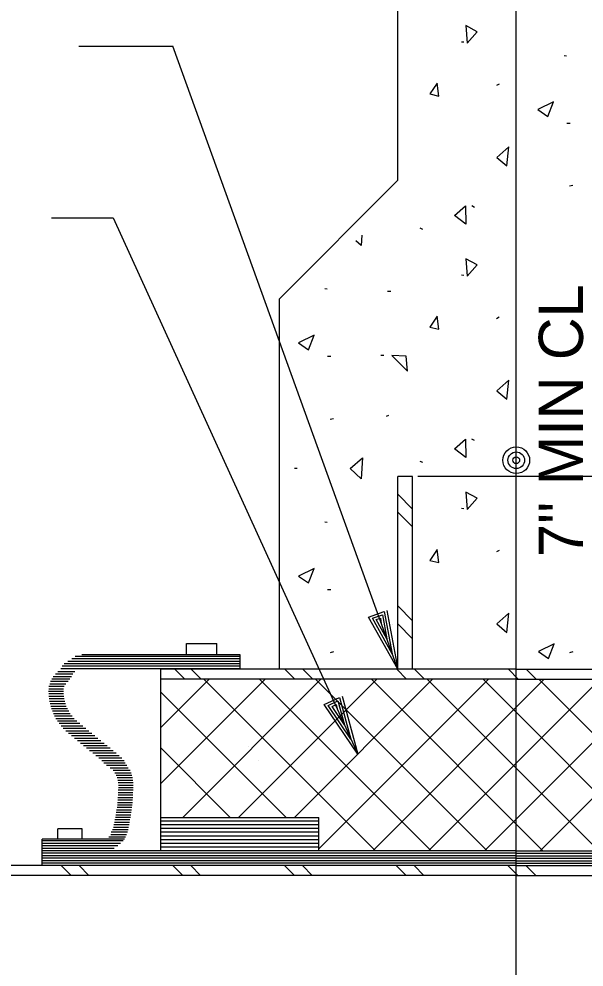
# Model space of a CAD drawing. Extents: x 22339.2 to 22413.4, y 22369.6 to 22418.8.
# Drawn here: x 22343.853 to 22346.238, y 22396.66 to 22400.659 of the extents above; entities that cross this region are included whole.
import ezdxf

# ---------------------------------------------------------------- set-up
doc = ezdxf.new("R2010")
doc.units = 0
for name, color, linetype in [('Level 1', 7, 'Continuous'), ('Level 2', 7, 'Continuous'), ('Level 4', 7, 'Continuous'), ('Level 44', 7, 'Continuous'), ('Level 7', 7, 'Continuous'), ('Level 8', 7, 'Continuous')]:
    doc.layers.add(name, color=color, linetype=linetype)

msp = doc.modelspace()

# ---------------------------------------------------------------- linework, layer by layer
at = {"layer": 'Level 1'}
for p, q in [((22345.9524, 22393.1147), (22345.9524, 22402.6063)), ((22345.4288, 22398.1058), (22345.4288, 22398.1058)), ((22344.5612, 22397.9773), (22344.5612, 22398.0249)), ((22344.5612, 22398.0249), (22344.6886, 22398.0249)), ((22344.6886, 22397.9773), (22344.6886, 22398.0249)), ((22345.4524, 22398.0406), (22345.4524, 22398.0406)), ((22344.4524, 22397.15), (22344.4524, 22397.9156)), ((22345.9524, 22397.9156), (22344.4524, 22397.9156)), ((22345.9524, 22397.9156), (22347.4524, 22397.9156)), ((22345.9524, 22397.874), (22344.4524, 22397.874)), ((22345.9524, 22397.874), (22347.4524, 22397.874)), ((22344.8216, 22397.5887), (22344.8216, 22397.5887)), ((22344.8627, 22397.5329), (22344.8627, 22397.5329)), ((22345.1191, 22397.275), (22344.4524, 22397.275)), ((22345.1191, 22397.2594), (22344.4524, 22397.2594)), ((22345.1191, 22397.2438), (22344.4524, 22397.2438)), ((22344.0172, 22397.1997), (22344.0172, 22397.2426)), ((22344.1208, 22397.2426), (22344.0172, 22397.2426)), ((22344.1208, 22397.1997), (22344.1208, 22397.2426)), ((22345.1191, 22397.2281), (22344.4524, 22397.2281)), ((22345.1191, 22397.2125), (22344.4524, 22397.2125)), ((22345.1191, 22397.1969), (22344.4524, 22397.1969)), ((22345.1191, 22397.1813), (22344.4524, 22397.1813)), ((22345.1191, 22397.1656), (22344.4524, 22397.1656))]:
    msp.add_line(p, q, dxfattribs=at)
at = {"layer": 'Level 2'}
for p, q in [((22344.1059, 22400.5431), (22344.5026, 22400.5431)), ((22345.4524, 22397.9156), (22344.5026, 22400.5431)), ((22345.4524, 22397.9156), (22345.4524, 22398.7281)), ((22345.5149, 22398.7281), (22345.4524, 22398.7281)), ((22345.5149, 22397.9156), (22345.5149, 22398.7281)), ((22346.4524, 22398.7281), (22345.5373, 22398.7281)), ((22344.7869, 22397.9773), (22344.1184, 22397.9773)), ((22344.7869, 22397.9156), (22344.7869, 22397.9773)), ((22344.4524, 22397.15), (22344.4524, 22397.2906)), ((22344.4524, 22397.2906), (22345.1191, 22397.2906)), ((22345.1191, 22397.15), (22345.1191, 22397.2906)), ((22343.9511, 22397.0875), (22343.9511, 22397.1997)), ((22344.2992, 22397.1997), (22343.9511, 22397.1997)), ((22345.9524, 22397.15), (22343.9511, 22397.15)), ((22345.9524, 22397.1396), (22343.9511, 22397.1396)), ((22345.9524, 22397.1292), (22343.9511, 22397.1292)), ((22345.9524, 22397.15), (22347.9537, 22397.15)), ((22345.9524, 22397.1396), (22347.9537, 22397.1396)), ((22345.9524, 22397.1292), (22347.9537, 22397.1292)), ((22345.9524, 22397.0875), (22339.2857, 22397.0875)), ((22345.9524, 22397.1188), (22343.9511, 22397.1188)), ((22345.9524, 22397.1083), (22343.9511, 22397.1083)), ((22345.9524, 22397.0979), (22343.9511, 22397.0979)), ((22345.9524, 22397.1188), (22347.9537, 22397.1188)), ((22345.9524, 22397.1083), (22347.9537, 22397.1083)), ((22345.9524, 22397.0979), (22347.9537, 22397.0979)), ((22345.9524, 22397.0875), (22352.5966, 22397.0875)), ((22345.9524, 22397.0458), (22339.315, 22397.0458)), ((22345.9524, 22397.0458), (22352.587, 22397.0458))]:
    msp.add_line(p, q, dxfattribs=at)
for points in [[(22343.9912, 22399.8197), (22344.2517, 22399.8197), (22345.2832, 22397.5579)], [(22345.4065, 22398.1642), (22345.4524, 22397.9156), (22345.3288, 22398.1361), (22345.3952, 22398.1601), (22345.4288, 22397.9808), (22345.3449, 22398.1306), (22345.3876, 22398.146), (22345.4062, 22398.0435), (22345.3611, 22398.1251), (22345.3787, 22398.1314), (22345.3826, 22398.1087)], [(22344.7857, 22397.9699), (22344.0912, 22397.9699)], [(22344.7857, 22397.9282), (22344.0363, 22397.9282)], [(22344.7857, 22397.9387), (22344.0449, 22397.9387)], [(22344.7857, 22397.9491), (22344.0601, 22397.9491)], [(22344.7857, 22397.9595), (22344.0759, 22397.9595)], [(22344.075, 22397.8844), (22343.9982, 22397.8844)], [(22344.0808, 22397.8948), (22344.0073, 22397.8948)], [(22344.0898, 22397.9052), (22344.0176, 22397.9052)], [(22344.7857, 22397.9178), (22344.0299, 22397.9178)], [(22344.0518, 22397.8531), (22343.9834, 22397.8531)], [(22344.0615, 22397.8636), (22343.986, 22397.8636)], [(22344.0686, 22397.874), (22343.9918, 22397.874)], [(22344.0411, 22397.8219), (22343.9786, 22397.8219)], [(22344.0415, 22397.8323), (22343.9789, 22397.8323)], [(22344.0415, 22397.8115), (22343.9789, 22397.8115)], [(22344.0415, 22397.8115), (22343.9789, 22397.8115)], [(22344.0446, 22397.8427), (22343.9796, 22397.8427)], [(22344.0425, 22397.8011), (22343.9796, 22397.8011)], [(22344.0425, 22397.8011), (22343.9796, 22397.8011)], [(22344.0441, 22397.7906), (22343.9808, 22397.7906)], [(22344.0441, 22397.7906), (22343.9808, 22397.7906)], [(22344.0465, 22397.7802), (22343.9825, 22397.7802)], [(22344.0465, 22397.7802), (22343.9825, 22397.7802)], [(22344.0495, 22397.7698), (22343.9847, 22397.7698)], [(22344.0495, 22397.7698), (22343.9847, 22397.7698)], [(22345.2173, 22397.8019), (22345.2832, 22397.5579), (22345.1421, 22397.7676), (22345.2064, 22397.7969), (22345.2544, 22397.621), (22345.1587, 22397.7634), (22345.1999, 22397.7823), (22345.2268, 22397.6817), (22345.1752, 22397.7593), (22345.1922, 22397.767), (22345.198, 22397.7447)], [(22344.0533, 22397.7594), (22343.9874, 22397.7594)], [(22344.058, 22397.749), (22343.9906, 22397.749)], [(22344.0635, 22397.7386), (22343.9944, 22397.7386)], [(22344.0701, 22397.7281), (22343.9987, 22397.7281)], [(22344.0778, 22397.7177), (22344.0037, 22397.7177)], [(22344.0869, 22397.7073), (22344.0094, 22397.7073)], [(22344.0977, 22397.6969), (22344.0158, 22397.6969)], [(22344.1102, 22397.6865), (22344.023, 22397.6865)], [(22344.123, 22397.6761), (22344.0311, 22397.6761)], [(22344.1358, 22397.6656), (22344.0402, 22397.6656)], [(22344.1485, 22397.6552), (22344.0506, 22397.6552)], [(22344.1613, 22397.6448), (22344.0625, 22397.6448)], [(22344.1741, 22397.6344), (22344.0752, 22397.6344)], [(22344.1868, 22397.624), (22344.088, 22397.624)], [(22344.1996, 22397.6136), (22344.1008, 22397.6136)], [(22344.2124, 22397.6031), (22344.1135, 22397.6031)], [(22344.2251, 22397.5927), (22344.1263, 22397.5927)], [(22344.2379, 22397.5823), (22344.139, 22397.5823)], [(22344.2507, 22397.5719), (22344.1518, 22397.5719)], [(22344.2634, 22397.5615), (22344.1646, 22397.5615)], [(22344.2762, 22397.5511), (22344.1774, 22397.5511)], [(22344.2875, 22397.5406), (22344.1901, 22397.5406)], [(22344.297, 22397.5302), (22344.2029, 22397.5302)], [(22344.3012, 22397.5198), (22344.2117, 22397.5198)], [(22344.3083, 22397.5094), (22344.2231, 22397.5094)], [(22344.3139, 22397.499), (22344.2387, 22397.499)], [(22344.3226, 22397.4886), (22344.2504, 22397.4886)], [(22344.3266, 22397.4781), (22344.2578, 22397.4781)], [(22344.3298, 22397.4677), (22344.2634, 22397.4677)], [(22344.3324, 22397.4573), (22344.2677, 22397.4573)], [(22344.3342, 22397.4469), (22344.2707, 22397.4469)], [(22344.3349, 22397.4052), (22344.2719, 22397.4052)], [(22344.3354, 22397.4365), (22344.2726, 22397.4365)], [(22344.3357, 22397.4156), (22344.2731, 22397.4156)], [(22344.3359, 22397.4261), (22344.2734, 22397.4261)], [(22344.333, 22397.3636), (22344.2704, 22397.3636)], [(22344.3336, 22397.374), (22344.271, 22397.374)], [(22344.3342, 22397.3844), (22344.2716, 22397.3844)], [(22344.3347, 22397.3948), (22344.2722, 22397.3948)], [(22344.3305, 22397.3323), (22344.2673, 22397.3323)], [(22344.3317, 22397.3427), (22344.2687, 22397.3427)], [(22344.3324, 22397.3531), (22344.2698, 22397.3531)], [(22344.3236, 22397.2906), (22344.2602, 22397.2906)], [(22344.3254, 22397.3011), (22344.2619, 22397.3011)], [(22344.3273, 22397.3115), (22344.2638, 22397.3115)], [(22344.329, 22397.3219), (22344.2656, 22397.3219)], [(22344.3163, 22397.249), (22344.2519, 22397.249)], [(22344.3183, 22397.2594), (22344.2544, 22397.2594)], [(22344.32, 22397.2698), (22344.2566, 22397.2698)], [(22344.3218, 22397.2802), (22344.2584, 22397.2802)], [(22344.3024, 22397.2073), (22344.2327, 22397.2073)], [(22344.3077, 22397.2177), (22344.2408, 22397.2177)], [(22344.3111, 22397.2281), (22344.2424, 22397.2281)], [(22344.3139, 22397.2386), (22344.2487, 22397.2386)], [(22344.2929, 22397.1917), (22343.9524, 22397.1917)], [(22344.2826, 22397.1813), (22343.9524, 22397.1813)], [(22344.2702, 22397.1708), (22343.9524, 22397.1708)], [(22344.2344, 22397.15), (22343.9511, 22397.15)], [(22344.2549, 22397.1604), (22343.9524, 22397.1604)]]:
    msp.add_lwpolyline(points, dxfattribs=at)
for radius in [0.0563, 0.0352, 0.0141]:
    msp.add_circle((22345.9523, 22398.7973), radius, dxfattribs=at)
at = {"layer": 'Level 44'}
for p, q in [((22345.7306, 22400.5604), (22345.7206, 22400.5612)), ((22346.1638, 22400.5019), (22346.1538, 22400.5037)), ((22345.8808, 22400.3842), (22345.8688, 22400.3782)), ((22346.1798, 22400.2182), (22346.1663, 22400.2182)), ((22346.1906, 22399.9564), (22346.1771, 22399.9527)), ((22345.7756, 22399.8639), (22345.7643, 22399.8707)), ((22345.5578, 22399.7709), (22345.5471, 22399.7759)), ((22345.7306, 22399.5767), (22345.7206, 22399.5774)), ((22345.1538, 22399.5182), (22345.1438, 22399.5199)), ((22345.4228, 22399.5097), (22345.4093, 22399.5097)), ((22345.8808, 22399.4004), (22345.8688, 22399.3944)), ((22345.1698, 22399.2344), (22345.1563, 22399.2344)), ((22345.3938, 22399.2392), (22345.3811, 22399.2392)), ((22345.1806, 22398.9727), (22345.1671, 22398.9689)), ((22345.4136, 22398.9862), (22345.4038, 22398.9824)), ((22345.7756, 22398.8802), (22345.7643, 22398.8869)), ((22345.0276, 22398.7632), (22345.0166, 22398.7622)), ((22345.5578, 22398.7872), (22345.5471, 22398.7922)), ((22345.7306, 22398.5929), (22345.7206, 22398.5937)), ((22345.1538, 22398.5344), (22345.1438, 22398.5362)), ((22345.8808, 22398.4167), (22345.8688, 22398.4107)), ((22345.1698, 22398.2507), (22345.1563, 22398.2507)), ((22345.1806, 22397.9889), (22345.1671, 22397.9852)), ((22346.1906, 22397.9889), (22346.1771, 22397.9852))]:
    msp.add_line(p, q, dxfattribs=at)
for points in [[(22345.7451, 22400.5569), (22345.7878, 22400.6049), (22345.7401, 22400.6304)], [(22345.6248, 22400.3334), (22345.6178, 22400.3882), (22345.5871, 22400.3424)], [(22346.0853, 22400.2474), (22346.1091, 22400.3087), (22346.0428, 22400.2764)], [(22345.9213, 22400.1192), (22345.8701, 22400.0744), (22345.9126, 22400.0387)], [(22345.7401, 22399.7932), (22345.6921, 22399.8294), (22345.7381, 22399.8702)], [(22345.7451, 22399.5732), (22345.7878, 22399.6212), (22345.7401, 22399.6467)], [(22345.6248, 22399.3497), (22345.6178, 22399.4044), (22345.5871, 22399.3587)], [(22345.0753, 22399.2637), (22345.0991, 22399.3249), (22345.0328, 22399.2927)], [(22345.4876, 22399.2359), (22345.4276, 22399.2392), (22345.4926, 22399.1727)], [(22345.9213, 22399.1354), (22345.8701, 22399.0907), (22345.9126, 22399.0549)], [(22345.7401, 22398.8094), (22345.6921, 22398.8457), (22345.7381, 22398.8864)], [(22345.2978, 22398.7192), (22345.2516, 22398.7619), (22345.3028, 22398.8077)], [(22345.7451, 22398.5894), (22345.7878, 22398.6374), (22345.7401, 22398.6629)], [(22345.6248, 22398.3659), (22345.6178, 22398.4207), (22345.5871, 22398.3749)], [(22345.0753, 22398.2799), (22345.0991, 22398.3412), (22345.0328, 22398.3089)], [(22345.9213, 22398.1517), (22345.8701, 22398.1069), (22345.9126, 22398.0712)], [(22346.0883, 22397.9618), (22346.112, 22398.0231), (22346.0458, 22397.9908)]]:
    msp.add_lwpolyline(points, close=True, dxfattribs=at)
msp.add_lwpolyline([(22345.3003, 22399.7467), (22345.2978, 22399.7029), (22345.2759, 22399.7231)], dxfattribs=at)
at = {"layer": 'Level 7'}
for p, q in [((22345.4524, 22399.9781), (22345.4524, 22401.8542)), ((22344.9524, 22399.4781), (22345.4524, 22399.9781)), ((22344.9524, 22397.9156), (22344.9524, 22399.4781))]:
    msp.add_line(p, q, dxfattribs=at)
at = {"layer": 'Level 8'}
for p, q in [((22345.2544, 22397.621), (22345.2544, 22397.621)), ((22345.2832, 22397.5579), (22345.2832, 22397.5579))]:
    msp.add_line(p, q, dxfattribs=at)
for points in [[(22345.5149, 22398.5914), (22345.4524, 22398.654)], [(22345.5149, 22398.516), (22345.4524, 22398.5785)], [(22345.5149, 22398.12), (22345.4524, 22398.1826)], [(22345.5149, 22398.0446), (22345.4524, 22398.1071)], [(22344.5534, 22397.874), (22344.5118, 22397.9156)], [(22344.6219, 22397.874), (22344.5802, 22397.9156)], [(22345.0179, 22397.874), (22344.9762, 22397.9156)], [(22345.0933, 22397.874), (22345.0517, 22397.9156)], [(22345.4893, 22397.874), (22345.4476, 22397.9156)], [(22345.5647, 22397.874), (22345.5231, 22397.9156)], [(22345.9607, 22397.874), (22345.919, 22397.9156)], [(22346.0361, 22397.874), (22345.9945, 22397.9156)], [(22344.4524, 22397.4342), (22344.8921, 22397.874)], [(22344.4524, 22397.6699), (22344.6564, 22397.874)], [(22344.5445, 22397.2906), (22345.1279, 22397.874)], [(22345.3576, 22397.15), (22344.6336, 22397.874)], [(22344.7802, 22397.2906), (22345.3635, 22397.874)], [(22345.5933, 22397.15), (22344.8693, 22397.874)], [(22345.0159, 22397.2906), (22345.5993, 22397.874)], [(22345.829, 22397.15), (22345.105, 22397.874)], [(22345.1191, 22397.1581), (22345.835, 22397.874)], [(22346.0647, 22397.15), (22345.3407, 22397.874)], [(22345.3467, 22397.15), (22346.0707, 22397.874)], [(22346.3004, 22397.15), (22345.5764, 22397.874)], [(22345.5824, 22397.15), (22346.3064, 22397.874)], [(22346.5361, 22397.15), (22345.8121, 22397.874)], [(22345.8181, 22397.15), (22346.5421, 22397.874)], [(22346.7718, 22397.15), (22346.0478, 22397.874)], [(22346.0538, 22397.15), (22346.7778, 22397.874)], [(22344.9812, 22397.2906), (22344.4524, 22397.8195)], [(22344.7455, 22397.2906), (22344.4524, 22397.5838)], [(22344.0732, 22397.0458), (22344.0315, 22397.0875)], [(22344.1486, 22397.0458), (22344.1069, 22397.0875)], [(22344.5446, 22397.0458), (22344.5029, 22397.0875)], [(22344.62, 22397.0458), (22344.5783, 22397.0875)], [(22345.016, 22397.0458), (22344.9743, 22397.0875)], [(22345.0914, 22397.0458), (22345.0497, 22397.0875)], [(22345.4874, 22397.0458), (22345.4457, 22397.0875)], [(22345.5628, 22397.0458), (22345.5211, 22397.0875)], [(22345.9588, 22397.0458), (22345.9171, 22397.0875)], [(22346.0342, 22397.0458), (22345.9925, 22397.0875)]]:
    msp.add_lwpolyline(points, dxfattribs=at)

# ---------------------------------------------------------------- texts
at = {"layer": 'Level 4'}
msp.add_text("7'' MIN CL ", height=0.186667, rotation=90, dxfattribs=at).set_placement((22346.2339, 22398.389))

doc.saveas('drawing.dxf')
